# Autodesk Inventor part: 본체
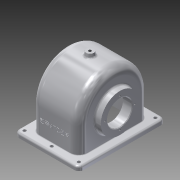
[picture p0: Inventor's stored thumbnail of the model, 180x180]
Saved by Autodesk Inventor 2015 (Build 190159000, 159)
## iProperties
Created: 2015-09
Part Number: 본체
Material: 알루미늄 6061
Document SubType Name: Modeling
Designer: PHO-1
Density: 2.7 g/cm^3
Appearance: 알루미늄 - 평지
Mass: 720.703 g
Surface Area: 889.376 cm^2
Volume: 266.927 cm^3
Author: PHO-1
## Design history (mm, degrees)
sketch "스케치2"
  geometry: L1 (-45, -70)-(45, -70); L2 (52, -63)-(52, 63); L3 (45, 70)-(-45, 70); L4 (-52, 63)-(-52, -63); L5 (-52, -70)-(52, 70); L6 (52, -70)-(-52, 70); A1 r 7 centre (-45, 63) between (-45, 70) and (-52, 63); A2 r 7 centre (45, 63) between (52, 63) and (45, 70); A3 r 7 centre (45, -63) between (45, -70) and (52, -63); A4 r 7 centre (-45, -63) between (-52, -63) and (-45, -70); 1 further point
  constraints: 12 end point, 8 point on circle, 8 point on line, 8 tangent, 4 centre point, 3 equal radius, 2 midpoint, 2 parallel, 1 horizontal, 1 perpendicular
  dimensions: "d2" = 7 radius of A1
extrude "돌출1" new body sketch "스케치2" distance "d3" = 7; taper "d4" = 0 deg
sketch "스케치3"
  geometry: L1 (44, -62)-(-44, -62); L2 (-44, -62)-(-44, 62); L3 (-44, 62)-(44, 62); L4 (44, 62)-(44, -62); 7 further points
  constraints: 8 end point, 4 coincident, 2 midpoint, 2 parallel, 1 horizontal, 1 perpendicular
  dimensions: "d5" = 88 distance of L2.end L3.end; "d6" = 124 distance of L1.end L2.end
hole "구멍1" sketch "스케치3" at (-44, 62), (0, 62), (44, 62), (44, -62), (0, -62), (-44, -62) diameter "d7" = 5; stored, may be unused: countersink angle "d11" = 90 deg, drill point angle "d13" = 0 deg; dims "d8" = 6, "d9" = 4, "d10" = 2, "d12" = 8
sketch "스케치4"
  geometry: L1 (59.5, 7)-(59.5, 0) reference; L2 (59.5, 0)-(-59.5, 0) reference; L3 (-59.5, 0)-(-59.5, 7) reference; L4 (-59.5, 7)-(59.5, 7) reference; L5 (-70, 0)-(-70, 7) reference; L6 (-70, 7)-(-64.5, 7) reference; L7 (-64.5, 7)-(-64.5, 0) reference; L8 (-64.5, 0)-(-70, 0) reference; L9 (70, 7)-(70, 0) reference; L10 (70, 0)-(64.5, 0) reference; L11 (64.5, 0)-(64.5, 7) reference; L12 (64.5, 7)-(70, 7) reference; L13 (57, 47)-(57, 7); L14 (-57, 7)-(-57, 47); A1 r 57 centre (0, 47) between (57, 47) and (-57, 47)
  constraints: 4 end point, 2 point on circle, 2 point on line, 1 centre point, 1 parallel
  dimensions: "d94" = 57 radius of A1
extrude "돌출2" join sketch "스케치4" stored distance "d19" = 77; taper "d20" = 0 deg
sketch "스케치5"
  geometry: L1 (59.5, 7)-(59.5, 0) reference; L2 (59.5, 0)-(-59.5, 0) reference; L3 (-59.5, 0)-(-59.5, 7) reference; L4 (-59.5, 7)-(-57, 7) reference; L5 (-57, 7)-(-57, 47) reference; L6 (57, 47)-(57, 7) reference; L7 (57, 7)-(59.5, 7) reference; L8 (-70, 0)-(-70, 7) reference; L9 (-70, 7)-(-64.5, 7) reference; L10 (-64.5, 7)-(-64.5, 0) reference; L11 (-64.5, 0)-(-70, 0) reference; L12 (70, 7)-(70, 0) reference; L13 (70, 0)-(64.5, 0) reference; L14 (64.5, 0)-(64.5, 7) reference; L15 (64.5, 7)-(70, 7) reference; L16 (-51, 47)-(-51, 0); L17 (51, 0)-(51, 47); A1 r 57 centre (0, 47) between (57, 47) and (-57, 47) reference; A2 r 51 centre (0, 47) between (51, 47) and (-51, 47); 1 further point
  constraints: 4 end point, 2 point on circle, 2 point on line, 1 centre point
  dimensions: "d21" = 6 radial gap between concentric circles of A1 A2
extrude "돌출3" cut sketch "스케치5" stored distance "d22" = 67; taper "d23" = 0 deg
sketch "스케치6"
  geometry: C1 r 31 at (-47, 0); 2 further points
  constraints: 1 centre point, 1 coincident
  dimensions: "d24" = 62 diameter of C1
extrude "돌출4" join sketch "스케치6" distance "d25" = 10; taper "d26" = 0 deg
node "작업 평면1"
sketch "스케치8"
  geometry: C1 r 28 at (-47, 0); 2 further points
  constraints: 1 centre point, 1 coincident
  dimensions: "d28" = 28 radius of C1
extrude "돌출5" join sketch "스케치8" stored distance "d29" = 10; taper "d30" = 40 deg
sketch "스케치10"
  geometry: L1 (38.5, 84.416)-(24.5, 72.668); L2 (24.5, 72.668)-(24.5, 47); L3 (38.5, 47)-(38.5, 84.416); L4 (38.5, 47)-(24.5, 47); 1 further point
  constraints: 8 end point, 1 point on line
revolve "회전1" sketch "스케치10" stored, may be unused: angle "d33" = 90 deg
sketch "스케치12"
  geometry: L1 (33.5, 47)-(-33.5, 47) reference; L2 (19.5, 47)-(35.5, 47); L3 (35.5, 47)-(35.5, 80); L4 (19.5, 75)-(19.5, 47); L5 (35.5, 80)-(33.237, 80); L6 (19.5, 75)-(33.237, 80); 1 further point
  constraints: 10 end point, 2 parallel, 1 horizontal, 1 perpendicular, 1 point on line
  dimensions: "d37" = 33 distance of L3.end L2.end
revolve "회전2" sketch "스케치12" stored, may be unused: angle "d38" = 90 deg
node "작업 평면4"
  node "작업 평면3"
sketch "스케치14"
  geometry: C1 r 6 at (0, 0); 1 further point
  constraints: 1 centre point, 1 coincident
  dimensions: "d40" = 6 radius of C1
extrude "돌출6" join sketch "스케치14" stored distance "d41" = 10; taper "d42" = 10 deg
sketch "스케치16"
  geometry: 2 further points
  constraints: 1 coincident
hole "구멍2" sketch "스케치16" at (0, 0) diameter "d43" = 4.459; stored, may be unused: countersink angle "d47" = 90 deg, drill point angle "d49" = 0 deg; dims "d44" = 15, "d45" = 4, "d46" = 2, "d48" = 12.8
sketch "스케치17"
  geometry: 2 further points
hole "구멍3" sketch "스케치17" at (0, 0) diameter "d50" = 40; stored, may be unused: countersink angle "d54" = 90 deg, drill point angle "d56" = 0 deg; dims "d51" = 15, "d52" = 4, "d53" = 2, "d55" = 12.8
sketch "스케치18"
  geometry: C1 r 20 at (0, 0) reference; C2 r 33 at (0, 0) reference; 5 further points
  constraints: 5 other
  dimensions: "d57" = 28 distance of C2.centre point (28, 0); "d60" = 360 deg dimension on C1.centre point (28, 0) (derived)
hole "구멍4" sketch "스케치18" at (28, 0), (0, 28), (-28, 0), (0, -28) diameter "d62" = 2.459; stored, may be unused: countersink angle "d66" = 90 deg, drill point angle "d68" = 118 deg; dims "d63" = 7, "d64" = 4, "d65" = 2, "d67" = 9
sketch "스케치19"
  geometry: C1 r 20 at (0, 0) reference; C2 r 31 at (0, 0) reference; 5 further points
  constraints: 5 other
  dimensions: "d69" = 24 distance of point (-24, 0) C1.centre; "d72" = 360 deg dimension on C1.centre point (-24, 0) (derived)
hole "구멍5" sketch "스케치19" at (-24, 0), (0, -24), (24, 0), (0, 24) diameter "d74" = 2.459; stored, may be unused: countersink angle "d78" = 90 deg, drill point angle "d80" = 118 deg; dims "d75" = 6, "d76" = 4, "d77" = 2, "d79" = 8
fillet "모깎기1" dims "d81" = 14, "d82" = 9, "d83" = 3
fillet "모깎기2" dims "d84" = 3, "d85" = 0.5, "d86" = 1
chamfer "모따기1" distance "d87" = 1; stored, may be unused: second distance "d88" = 2, angle "d89" = 45 deg
sketch "스케치20"
  geometry: L1 (-14, 0)-(-14, -39) reference; L2 (69.5, -47)-(-20.5, -47) reference; 2 further points
  constraints: 1 other
  dimensions: "d90" = 38.5 distance from line of L1 point (24.5, -17); "d91" = 30 distance from line of L2 point (24.5, -17)
feature "엠보싱1" sketch "스케치20" dims "d2" = 7, "d7" = 5, "d92" = 0.5, "d93" = 0
node "솔리드1"
node "투영된 루프4"
node "투영된 루프5"
node "절단 모서리 투영1"
node "절단 모서리 투영2"
other parameters: "d27" = 14, "d39" = 6
